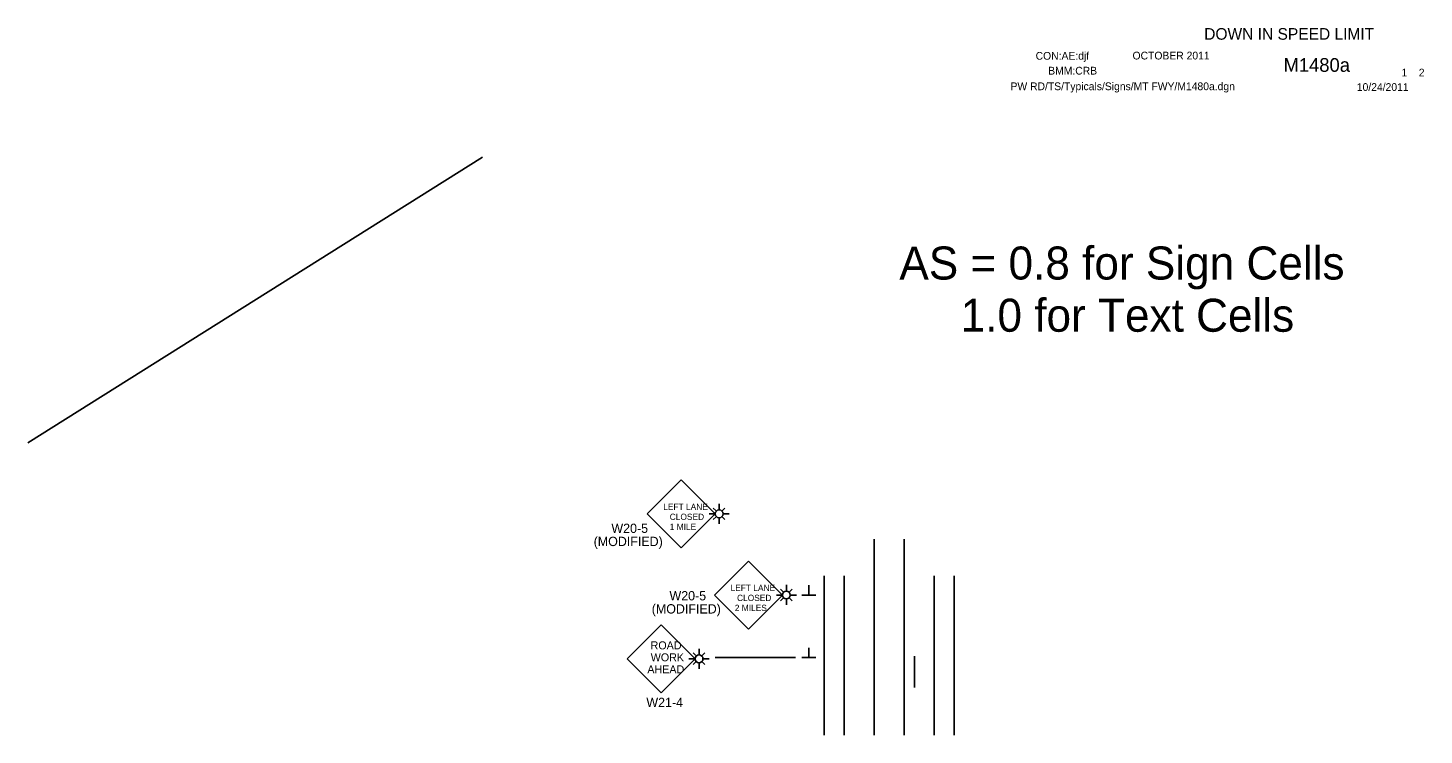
# Model space of a CAD drawing. Extents: x 16284 to 18468, y 5417 to 6974.
# Drawn here: x 16284 to 17402, y 5417 to 5984 of the extents above; entities that cross this region are included whole.
import ezdxf

# ---------------------------------------------------------------- set-up
doc = ezdxf.new("R2010")
doc.units = 0
for name, color, linetype in [('ALI_LEGAL_EX', 7, 'Continuous'), ('BORDER', 7, 'Continuous'), ('BORDER_SIGNAL_WO', 7, 'Continuous'), ('PAVT_EDGE_EX', 7, 'Continuous'), ('TRAFFIC_SIGNS_PR', 7, 'Continuous'), ('TYPICAL_TEXT_DIMEN_PR', 7, 'Continuous')]:
    doc.layers.add(name, color=color, linetype=linetype)

msp = doc.modelspace()

# ---------------------------------------------------------------- linework, layer by layer
at = {"layer": 'ALI_LEGAL_EX'}
for p, q in [((16961.5, 5574.3), (16961.5, 5417.4)), ((16985.5, 5574.3), (16985.5, 5417.4))]:
    msp.add_line(p, q, dxfattribs=at)
for points in [[(16961.5, 5544.9), (16961.5, 5519.9)], [(16985.5, 5544.9), (16985.5, 5519.9)], [(16993.6, 5480.5), (16993.6, 5455.5)], [(16961.5, 5444.9), (16961.5, 5419.9)], [(16985.5, 5444.9), (16985.5, 5419.9)]]:
    msp.add_lwpolyline(points, dxfattribs=at)
at = {"layer": 'PAVT_EDGE_EX'}
for p, q in [((16921.5, 5544.9), (16921.5, 5417.4)), ((16937.5, 5544.9), (16937.5, 5417.4)), ((17009.5, 5544.9), (17009.5, 5417.4)), ((17025.5, 5544.9), (17025.5, 5417.4))]:
    msp.add_line(p, q, dxfattribs=at)
at = {"layer": 'TRAFFIC_SIGNS_PR'}
for p, q in [((16806.9, 5621.7), (16779.7, 5594.5)), ((16834.1, 5594.5), (16806.9, 5621.7)), ((16837.3, 5598), (16837.3, 5602.5)), ((16779.7, 5594.5), (16806.9, 5567.3)), ((16806.9, 5567.3), (16834.1, 5594.5)), ((16834.1, 5594.5), (16829.2, 5594.5)), ((16834.8, 5597), (16832.6, 5599.1)), ((16834.8, 5592), (16832.6, 5589.9)), ((16837.3, 5586.5), (16837.3, 5590.9)), ((16839.8, 5597), (16841.9, 5599.1)), ((16839.8, 5592), (16841.9, 5589.9)), ((16840.4, 5594.5), (16845.3, 5594.5)), ((16860.8, 5556.7), (16833.6, 5529.5)), ((16887.9, 5529.5), (16860.8, 5556.7)), ((16888.6, 5532), (16886.5, 5534.1)), ((16891.1, 5533.1), (16891.1, 5537.6)), ((16893.6, 5532), (16895.7, 5534.1)), ((16833.6, 5529.5), (16860.8, 5502.3)), ((16860.8, 5502.3), (16887.9, 5529.5)), ((16887.9, 5529.5), (16883.1, 5529.5)), ((16888.6, 5527), (16886.5, 5524.9)), ((16891.1, 5521.6), (16891.1, 5526)), ((16893.6, 5527), (16895.7, 5524.9)), ((16894.2, 5529.5), (16899.1, 5529.5)), ((16790.8, 5505.6), (16763.7, 5478.4)), ((16818, 5478.4), (16790.8, 5505.6)), ((16763.7, 5478.4), (16790.8, 5451.3)), ((16790.8, 5451.3), (16818, 5478.4)), ((16818, 5478.4), (16813.1, 5478.4)), ((16818.7, 5481), (16816.6, 5483.1)), ((16821.2, 5482), (16821.2, 5486.5)), ((16823.7, 5481), (16825.8, 5483.1)), ((16824.3, 5478.4), (16829.2, 5478.4)), ((16818.7, 5475.9), (16816.6, 5473.8)), ((16821.2, 5470.5), (16821.2, 5474.9)), ((16823.7, 5475.9), (16825.8, 5473.8))]:
    msp.add_line(p, q, dxfattribs=at)
for centre in [(16837.3, 5594.5), (16891.1, 5529.5), (16821.2, 5478.4)]:
    msp.add_circle(centre, 3.15, dxfattribs=at)
at = {"layer": 'TYPICAL_TEXT_DIMEN_PR'}
for p, q in [((16647.8, 5880), (16283.8, 5651.4)), ((16909.1, 5529.5), (16909.1, 5537.3)), ((16903.5, 5529.5), (16914.8, 5529.5)), ((16834.1, 5479.5), (16898.5, 5479.5)), ((16903.5, 5479.5), (16914.8, 5479.5)), ((16909.1, 5479.5), (16909.1, 5487.3))]:
    msp.add_line(p, q, dxfattribs=at)

# ---------------------------------------------------------------- texts
at = {"layer": 'BORDER'}
msp.add_text('DOWN IN SPEED LIMIT', height=9.3, dxfattribs=at).set_placement((17225.7, 5974.1))
at = {"layer": 'BORDER_SIGNAL_WO'}
for s, height, p in [('CON:AE:djf  ', 6.2, (17090.7, 5958.1)), ('    OCTOBER 2011    ', 6.2, (17159.1, 5958.3)), ('    M1480a   ', 11, (17272.9, 5948.4)), ('BMM:CRB   ', 6.2, (17100.8, 5946.2)), (' 1    2 ', 6.2, (17381.4, 5944.7)), ('PW RD/TS/Typicals/Signs/MT FWY/M1480a.dgn      ', 6.2, (17070.6, 5933.7)), ('10/24/2011    ', 6.2, (17347.9, 5933.1)), ('AS = 0.8 for Sign Cells', 26.424, (16981.6, 5782.1)), ('     1.0 for Text Cells', 26.424, (16981.6, 5740.3))]:
    msp.add_text(s, height=height, dxfattribs=at).set_placement(p)
at = {"layer": 'TRAFFIC_SIGNS_PR'}
for s, height, p in [('LEFT LANE', 5.01, (16792.5, 5597.6)), ('CLOSED', 5.01, (16797.7, 5589.6)), ('W20-5', 7.45, (16751, 5579.2)), ('1 MILE', 5.01, (16797.7, 5581.6)), ('(MODIFIED)', 7.45, (16736.8, 5568.7)), ('LEFT LANE', 5.01, (16846.4, 5532.7)), ('W20-5', 7.45, (16797.5, 5525.2)), ('CLOSED', 5.01, (16851.6, 5524.7)), ('(MODIFIED)', 7.45, (16783.3, 5514.7)), ('2 MILES', 5.01, (16849.8, 5516.7)), ('ROAD', 6.41, (16782.4, 5486)), ('WORK', 6.41, (16782.5, 5476.4)), ('AHEAD', 6.41, (16779.8, 5466.8)), ('W21-4', 7.45, (16779, 5439.8))]:
    msp.add_text(s, height=height, dxfattribs=at).set_placement(p)

doc.saveas('drawing.dxf')
